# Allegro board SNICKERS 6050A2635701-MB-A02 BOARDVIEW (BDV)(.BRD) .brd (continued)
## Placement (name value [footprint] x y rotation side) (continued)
R3076  10K_5%_2  [RSC_100X050X040_2]  89.19 86.85 90 bottom
R3077  0_5%_2_DY  [RSC_100X050X040_2]  93.89 89.14 180 bottom
R3078  10K_5%_2_DY  [RSC_100X050X040_2]  77.56 86.74 180 top
R3081  0_5%_2  [RSC_100X050X040_2]  91 87.2 90 bottom
R3082  0_5%_2  [RSC_100X050X040_2]  76.49 89.14 270 top
R3083  0_5%_2  [RSC_100X050X040_2]  74.71 89.14 270 top
R3092  0_5%_2  [RSC_100X050X040_2]  91.46 91.67 180 top
R3093  10K_5%_2_DY  [RSC_100X050X040_2]  76.23 86.85 90 top
R3094  10K_5%_2_DY  [RSC_100X050X040_2]  77.38 89.14 90 top
R3095  10K_5%_2_DY  [RSC_100X050X040_2]  75.6 89.14 90 top
R3301  100K_5%_2  [RSC_100X050X040_2]  317.91 25.89 0 bottom
R3302  5.1M_5%_2  [RSC_100X050X040_2]  317.91 25 180 bottom
R3303  100K_5%_2  [RSC_100X050X040_2]  317.91 27.67 180 bottom
R3304  1M_5%_2  [RSC_100X050X040_2]  317.91 28.56 180 bottom
R3305  100_5%_2  [RSC_100X050X040_2]  315.5 41.01 90 top
R3501  0_5%_2_DY  [RSC_100X050X040_2]  124.49 147.43 270 top
R3502  4.7K_5%_2  [RSC_100X050X040_2]  126.65 147.43 90 top
R3503  4.7K_5%_2  [RSC_100X050X040_2]  129.19 146.92 90 bottom
R3507  0_5%_2_DY  [RSC_100X050X040_2]  122.71 147.43 270 top
R3510  0_5%_2_DY  [RSC_100X050X040_2]  130.21 147.43 90 top
R3511  short_0402_15  [RSC_100X050X040_2_15_SHORT]  128.43 147.43 90 top
R3516  0_5%_2_DY  [RSC_100X050X040_2]  129.32 147.43 90 top
R3600  0_5%_2  [RSC_100X050X040_2]  311.31 118.22 0 top
R4100  10K_5%_2  [RSC_100X050X040_2]  200.44 135.11 180 top
R4101  10K_5%_2  [RSC_100X050X040_2]  203.74 134.22 0 top
R4103  10K_5%_2_DY  [RSC_100X050X040_2]  202.09 134.22 0 top
R4104  0_5%_2_DY  [RSC_100X050X040_2]  206.79 145.02 0 top
R4105  2_1%_2  [RSC_100X050X040_2]  252.64 142.23 270 top
R4106  1.8K_1%_2  [RSC_100X050X040_2]  211.74 144.77 90 top
R4107  0_5%_2_DY  [RSC_100X050X040_2]  253.52 142.23 90 top
R4108  1.8K_1%_2  [RSC_100X050X040_2]  255.3 142.23 270 top
R4109  1.8K_1%_2  [RSC_100X050X040_2]  259.11 142.23 90 top
R4110  24.9_1%_2  [RSC_100X050X035_2]  249.59 141.72 90 top
R4111  24.9_1%_2  [RSC_100X050X035_2]  189.9 146.92 0 top
R4112  2_1%_2  [RSC_100X050X040_2]  188.25 146.04 0 top
R4114  10K_5%_2  [RSC_100X050X040_2]  178.21 147.31 270 top
R4115  10K_5%_2_DY  [RSC_100X050X040_2]  178.21 145.65 270 top
R4116  10K_5%_2  [RSC_100X050X040_2]  131.73 147.43 270 top
R4117  64.9_1%_2  [RSC_100X050X040_2]  223.93 143.37 0 top
R4118  64.9_1%_2  [RSC_100X050X040_2]  223.93 142.48 0 top
R4119  64.9_1%_2  [RSC_100X050X040_2]  149.38 147.31 270 bottom
R4120  64.9_1%_2  [RSC_100X050X040_2]  147.73 147.31 270 bottom
R4121  330_5%_2  [RSC_100X050X040_2]  132.87 147.43 270 top
R4122  1.8K_1%_2  [RSC_100X050X040_2]  210.85 144.77 270 top
R4123  100K_5%_2  [RSC_100X050X040_2]  129.45 144.89 90 top
R4125  10K_5%_2  [RSC_100X050X040_2]  125.46 134.94 0 top
R4126  10K_5%_2  [RSC_100X050X040_2]  123.83 134.94 180 top
R4131  1.8K_1%_2  [RSC_100X050X040_2]  188.25 146.92 180 top
R4132  1.8K_1%_2  [RSC_100X050X040_2]  185.83 146.04 180 top
R4134  0_5%_2_DY  [RSC_100X050X040_2]  188.25 145.15 180 top
R4136  24.9_1%_2  [RSC_100X050X035_2]  227.36 101.08 0 top
R4200  10K_5%_2  [RSC_100X050X040_2]  123.86 139.69 0 top
R4301  10K_5%_2  [RSC_100X050X040_2]  115.09 161.28 0 bottom
R4302  22_5%_2  [RSC_100X050X040_2]  115.09 159.5 180 bottom
R4303  10K_5%_2  [RSC_100X050X040_2]  117.13 157.34 0 bottom
R4411  39K_1%_2  [RSC_100X050X040_2]  48.93 88.63 270 top
R4412  150_1%_2  [RSC_100X050X040_2]  49.82 85.84 90 top
R4503  2_1%_2  [RSC_100X050X040_2]  227.36 103.11 180 top
R4507  51_5%_2_DY  [RSC_100X050X040_2]  223.36 75.47 0 top
R4508  51_5%_2_DY  [RSC_100X050X040_2]  223.35 77.82 0 top
R4509  51_5%_2  [RSC_100X050X040_2]  223.36 72.74 180 top
R4515  56_5%_2  [RSC_100X050X040_2]  223.3 79.87 180 top
R4516  100K_5%_2_DY  [RSC_100X050X040_2]  223.81 84.69 180 top
R4517  62_5%_2  [RSC_100X050X040_2]  225.08 79.61 180 top
R4518  200_1%_2  [RSC_100X050X040_2]  218.43 93.15 90 bottom
R4519  49.9_1%_2  [RSC_100X050X040_2]  211.49 83.68 0 top
R4520  49.9_1%_2  [RSC_100X050X040_2]  186.34 95.87 0 top
R4521  100_1%_2  [RSC_100X050X040_2]  211.49 74.15 90 top
R4522  100_1%_2  [RSC_100X050X040_2]  212.5 74.15 90 top
R4523  1K_5%_2  [RSC_100X050X040_2]  209.96 86.85 180 top
R4524  75_1%_2  [RSC_100X050X040_2]  212.12 78.09 0 top
R4525  43_5%_2  [RSC_100X050X040_2]  212.24 79.43 270 top
R4526  51_5%_2_DY  [RSC_100X050X040_2]  225.08 93.97 0 top
R4527  10K_5%_2_DY  [RSC_100X050X040_2]  216.82 72.25 180 bottom
R4534  1K_1%_2_DY  [RSC_100X050X040_2]  211.74 85.2 180 top
R4535  short_0402_15  [RSC_100X050X040_2_15_SHORT]  158.4 85.96 0 top
R4540  100_1%_2  [RSC_100X050X040_2]  217.53 93.15 90 bottom
R4541  120_1%_2  [RSC_100X050X040_2]  219.34 93.15 90 bottom
R4544  24.9_1%_2  [RSC_100X050X035_2]  186.72 70.34 270 bottom
R4550  short_0402_5  [RSC_100X050X040_2_SHORT]  141.51 100.7 270 top
R4553  470_5%_2  [RSC_100X050X040_2]  148.75 92.82 180 bottom
R4568  0_5%_2_DY  [RSC_100X050X040_2]  223.36 71.81 0 top
R4569  short_0402_15  [RSC_100X050X040_2_15_SHORT]  223.36 74.55 0 top
R4571  10K_5%_2  [RSC_100X050X040_2]  164.24 74.28 0 top
R4572  10K_5%_2_DY  [RSC_100X050X040_2]  164.75 77.91 180 top
R4573  8.2K_5%_2  [RSC_100X050X040_2]  158.4 78.79 0 top
R4574  8.2K_5%_2_DY  [RSC_100X050X040_2]  158.4 77.9 0 top
R4575  8.2K_5%_2_DY  [RSC_100X050X040_2]  163.1 79.23 0 bottom
R4576  8.2K_5%_2  [RSC_100X050X040_2]  162.59 78.34 0 bottom
R4577  8.2K_5%_2_DY  [RSC_100X050X040_2]  158.47 79.49 0 bottom
R4578  8.2K_5%_2  [RSC_100X050X040_2]  158.47 78.58 0 bottom
R4588  short_0402_5  [RSC_100X050X040_2_SHORT]  142.91 100.19 180 bottom
R4590  150_5%_2  [RSC_100X050X040_2]  223.35 76.53 0 top
R4593  10K_5%_2  [RSC_100X050X040_2]  216.82 71.36 0 bottom
R4700  10K_5%_2  [RSC_100X050X040_2]  168.82 94.85 0 bottom
R4701  short_0402_15  [RSC_100X050X040_2_15_SHORT]  153.83 80.12 180 top
R4705  10K_5%_2  [RSC_100X050X040_2]  153.83 76.31 0 bottom
R4706  10K_5%_2_DY  [RSC_100X050X040_2]  163.02 83.02 0 bottom
R4707  10K_5%_2  [RSC_100X050X040_2]  163.1 80.25 0 bottom
R4708  10K_5%_2  [RSC_100X050X040_2]  158.47 85.1 180 bottom
R4709  10K_5%_2  [RSC_100X050X040_2]  163.02 85.81 0 bottom
R4711  10K_5%_2  [RSC_100X050X040_2]  158.4 79.68 0 top
R4712  10K_5%_2  [RSC_100X050X040_2]  153.83 83.17 0 top
R4713  100K_5%_2  [RSC_100X050X040_2]  142.15 88.38 0 bottom
R4714  10K_5%_2  [RSC_100X050X040_2]  168.82 96.63 0 bottom
R4715  10K_5%_2  [RSC_100X050X040_2]  158.47 81.34 0 bottom
R4717  10K_5%_2  [RSC_100X050X040_2]  153.83 91.93 180 top
R4718  short_0402_5  [RSC_100X050X040_2_SHORT]  158.4 92.95 180 top
R4720  10K_5%_2_DY  [RSC_100X050X040_2]  166.15 94.73 0 bottom
R4721  10K_5%_2_DY  [RSC_100X050X040_2]  158.45 96.1 0 bottom
R4722  0_5%_2_DY  [RSC_100X050X040_2]  158.39 83.29 0 top
R4723  short_0402_5  [RSC_100X050X040_2_SHORT]  158.39 82.4 0 top
R4724  10K_5%_2  [RSC_100X050X040_2]  163.01 94.29 0 bottom
R4725  10K_5%_2  [RSC_100X050X040_2]  158.39 84.18 0 top
R4726  10K_5%_2_DY  [RSC_100X050X040_2]  170.85 81.9 180 top
R4727  8.2K_5%_2  [RSC_100X050X040_2]  158.47 84.17 180 bottom
R4728  10K_5%_2  [RSC_100X050X040_2]  153.83 78.34 0 top
R4729  200K_5%_2  [RSC_100X050X040_2]  158.47 86.93 0 bottom
R4730  10K_5%_2_DY  [RSC_100X050X040_2]  158.47 76.72 180 bottom
R4731  10K_5%_2  [RSC_100X050X040_2]  158.47 77.64 180 bottom
R4732  1K_5%_2  [RSC_100X050X040_2]  223.36 73.66 0 top
R4733  1K_5%_2  [RSC_100X050X040_2]  158.46 89.72 0 bottom
R4734  10K_5%_2  [RSC_100X050X040_2]  163.01 92.45 0 bottom
R4735  10K_5%_2  [RSC_100X050X040_2]  166.78 73.52 180 bottom
R4736  10K_5%_2  [RSC_100X050X040_2]  158.32 95.21 0 bottom
R4737  10K_5%_2_DY  [RSC_100X050X040_2]  158.45 92.42 180 bottom
R4738  10K_5%_2  [RSC_100X050X040_2]  153.83 75.68 180 top
R4741  10K_5%_2  [RSC_100X050X040_2]  158.45 91.53 0 bottom
R4742  330K_5%_2  [RSC_100X050X040_2]  173.26 100.44 0 bottom
R4743  100K_5%_2  [RSC_100X050X040_2]  158.4 95.87 0 top
R4744  10K_5%_2  [RSC_100X050X040_2]  158.45 96.99 0 bottom
R4745  10K_5%_2  [RSC_100X050X040_2]  153.83 74.79 180 top
R4746  100K_5%_2_DY  [RSC_100X050X040_2]  166.15 98.54 0 bottom
R4747  10K_5%_2  [RSC_100X050X040_2]  158.45 93.43 0 bottom
R4748  49.9_1%_2  [RSC_100X050X040_2]  186.34 94.47 0 top
R4749  10K_5%_2  [RSC_100X050X040_2]  158.66 74.41 0 top
R4750  10K_5%_2  [RSC_100X050X040_2]  169.83 71.61 180 bottom
R4751  10K_5%_2_DY  [RSC_100X050X040_2]  158.47 80.41 0 bottom
R4752  10K_5%_2  [RSC_100X050X040_2]  166.78 71.23 180 bottom
R4753  10K_5%_2  [RSC_100X050X040_2]  163.02 84.88 0 bottom
R4754  10K_5%_2  [RSC_100X050X040_2]  153.83 77.46 180 top
R4755  10K_5%_2  [RSC_100X050X040_2]  158.4 72.76 180 bottom
R4756  22.6_1%_2  [RSC_100X050X040_2]  158.4 94.98 180 top
R4757  10K_5%_2  [RSC_100X050X040_2]  153.83 72.76 180 bottom
R4758  100K_5%_2  [RSC_100X050X040_2]  167.55 69.45 180 bottom
R4759  100K_5%_2  [RSC_100X050X040_2]  168.56 66.79 180 bottom
R4760  10K_5%_2_DY  [RSC_100X050X040_2]  153.83 73.65 180 bottom
R4761  10K_5%_2_DY  [RSC_100X050X040_2]  153.83 74.53 180 bottom
R4762  10K_5%_2_DY  [RSC_100X050X040_2]  153.83 71.87 180 bottom
R4763  10K_5%_2  [RSC_100X050X040_2]  153.83 70.98 180 bottom
R4764  10K_5%_2  [RSC_100X050X040_2]  153.83 79.23 180 top
R4765  10K_5%_2  [RSC_100X050X040_2]  158.47 83.25 180 bottom
R4767  10K_5%_2_DY  [RSC_100X050X040_2]  170.85 82.79 180 top
R4769  10K_5%_2_DY  [RSC_100X050X040_2]  169.83 70.72 0 bottom
R4770  10K_5%_2  [RSC_100X050X040_2]  164.24 76.06 0 top
R4771  10K_5%_2  [RSC_100X050X040_2]  172.24 60.95 180 top
R4774  22_5%_2  [RSC_100X050X040_2]  164.24 106.69 270 top
R4775  10K_5%_2  [RSC_100X050X040_2]  193.71 69.71 180 bottom
R4776  2.2K_5%_2  [RSC_100X050X040_2]  153.83 88.63 0 bottom
R4778  10K_5%_2  [RSC_100X050X040_2]  166.15 97.65 180 bottom
R4780  10K_5%_2  [RSC_100X050X040_2]  169.83 69.71 0 bottom
R4781  8.2K_5%_2  [RSC_100X050X040_2]  164.24 75.17 0 top
R4782  10K_5%_2  [RSC_100X050X040_2]  261.02 76.57 0 bottom
R4783  2.2K_5%_2  [RSC_100X050X040_2]  148.88 86.98 180 bottom
R4785  10K_5%_2  [RSC_100X050X040_2]  153.83 76.57 180 top
R4786  2.2K_5%_2  [RSC_100X050X040_2]  175.17 69.38 180 bottom
R4787  2.2K_5%_2  [RSC_100X050X040_2]  171.74 66.79 180 bottom
R4788  2.2K_5%_2  [RSC_100X050X040_2]  168.56 67.68 180 bottom
R4789  2.2K_5%_2  [RSC_100X050X040_2]  175.17 68.49 180 bottom
R4790  short_0402_5  [RSC_100X050X040_2_SHORT]  146.59 82.49 0 bottom
R4791  10K_5%_2  [RSC_100X050X040_2]  193.71 70.6 180 bottom
R4792  2.2K_5%_2  [RSC_100X050X040_2]  153.83 83.93 180 bottom
R4793  33_5%_2  [RSC_100X050X040_2]  164.98 81.97 0 bottom
R4794  33_5%_2  [RSC_100X050X040_2]  158.46 87.87 0 bottom
R4795  33_5%_2  [RSC_100X050X040_2]  166.57 88.83 0 bottom
R4796  33_5%_2  [RSC_100X050X040_2]  163.02 87.64 0 bottom
R4797  2.2K_5%_2  [RSC_100X050X040_2]  148.88 88.38 0 bottom
R4798  10K_5%_2  [RSC_100X050X040_2]  163.01 89.46 0 bottom
R4799  short_0402_5  [RSC_100X050X040_2_SHORT]  167.67 86.47 90 top
R4800  10K_5%_2  [RSC_100X050X040_2]  153.83 95.36 0 top
R4801  10K_5%_2  [RSC_100X050X040_2]  155.45 95.36 180 top
R4802  short_0402_5  [RSC_100X050X040_2_SHORT]  163.01 90.35 0 bottom
R4803  10K_5%_2  [RSC_100X050X040_2]  158.66 72.63 0 top
R4804  10K_5%_2  [RSC_100X050X040_2]  158.66 73.52 0 top
R4805  10K_5%_2  [RSC_100X050X040_2]  158.66 71.74 0 top
R4806  10K_5%_2_DY  [RSC_100X050X040_2]  153.83 79.87 180 bottom
R4807  51_5%_2  [RSC_100X050X040_2]  211.74 86.6 180 top
R4808  51_5%_2_DY  [RSC_100X050X040_2]  240.32 88.63 0 top
R4809  10K_5%_2_DY  [RSC_100X050X040_2]  153.83 78.09 180 bottom
R4810  10K_5%_2  [RSC_100X050X040_2]  153.83 80.76 180 bottom
R4811  0_5%_2  [RSC_100X050X040_2]  186.6 66.66 270 bottom
R4812  3K_1%_2  [RSC_100X050X040_2]  186.72 68.31 90 bottom
R4813  10K_5%_2  [RSC_100X050X040_2]  153.83 77.2 180 bottom
R4814  10K_5%_2_DY  [RSC_100X050X040_2]  153.83 78.98 180 bottom
R4815  short_0402_5  [RSC_100X050X040_2_SHORT]  166.15 99.43 180 bottom
R4816  10K_5%_2  [RSC_100X050X040_2]  163.02 82.09 0 bottom
R4817  10K_5%_2  [RSC_100X050X040_2]  163.02 81.16 180 bottom
R4818  10K_5%_2  [RSC_100X050X040_2]  163.02 83.96 0 bottom
R4820  43K_1%_2  [RSC_100X050X040_2]  163.01 88.58 180 bottom
R4821  110_1%_2  [RSC_100X050X040_2]  212.12 80.88 0 top
R4822  short_0402_5  [RSC_100X050X040_2_SHORT]  240.19 91.17 180 top
R4823  1K_5%_2  [RSC_100X050X040_2]  240.19 90.28 0 top
R4824  10K_5%_2_DY  [RSC_100X050X040_2]  164.75 88.63 0 bottom
R4825  10K_5%_2  [RSC_100X050X040_2]  162.97 98.28 180 bottom
R4827  2.2K_5%_2  [RSC_100X050X040_2]  144.05 85.84 0 bottom
R4828  2.2K_5%_2  [RSC_100X050X040_2]  148.89 84.55 180 bottom
R4829  2.2K_5%_2_DY  [RSC_100X050X040_2]  153.83 92.95 180 top
R4830  2.2K_5%_2  [RSC_100X050X040_2]  148.88 85.46 0 bottom
R4831  1M_5%_2  [RSC_100X050X040_2]  144.94 99.68 0 bottom
R4832  1K_5%_2  [RSC_100X050X040_2]  141.38 101.2 0 bottom
R4833  1M_5%_2  [RSC_100X050X040_2]  144.94 100.57 0 bottom
R4834  20K_5%_2  [RSC_100X050X040_2]  145.45 102.09 180 bottom
R4835  0_5%_2_DY  [RSC_100X050X040_2]  153.83 86.09 0 bottom
R4836  0_5%_2_DY  [RSC_100X050X040_2]  148.88 83.55 0 bottom
R4838  2.2K_5%_2_DY  [RSC_100X050X040_2]  254.03 100.06 180 top
R4839  10K_5%_2  [RSC_100X050X040_2]  263.68 59.8 90 top
R4840  10K_5%_2  [RSC_100X050X040_2]  166.15 96.76 180 bottom
R4841  8.2K_5%_2  [RSC_100X050X040_2]  180.25 75.04 270 top
R4842  330K_5%_2  [RSC_100X050X040_2]  173.26 101.33 0 bottom
R4845  33K_5%_2  [RSC_100X050X040_2]  144.94 98.79 0 bottom
R4850  0_5%_2_DY  [RSC_100X050X040_2]  181.01 80 180 top
R4852  3.01K_1%_2  [RSC_100X050X040_2]  179.1 70.34 270 bottom
R4855  0_5%_2_DY  [RSC_100X050X040_2]  172.24 83.81 180 top
R4856  2.2K_5%_2  [RSC_100X050X040_2]  144.05 84.69 180 bottom
R4857  10K_5%_2  [RSC_100X050X040_2]  168.82 95.74 0 bottom
R4858  0_5%_3  [RSC_160X080X055_2]  189.39 81.65 90 top
R4859  10K_5%_2  [RSC_100X050X040_2]  166.78 72.12 180 bottom
R4860  short_0402_5  [RSC_100X050X040_2_SHORT]  162.97 96.51 0 bottom
R4861  1K_5%_2  [RSC_100X050X040_2]  151.54 106.54 0 top
R4862  10M_5%_2  [RSC_100X050X040_2]  165.77 102.09 270 bottom
R4863  10K_5%_2  [RSC_100X050X040_2]  151.54 107.94 0 top
R4866  short_0402_5  [RSC_100X050X040_2_SHORT]  153.83 81.65 0 bottom
R4867  1K_5%_2  [RSC_100X050X040_2]  151.8 80 90 bottom
R4868  short_0402_5  [RSC_100X050X040_2_SHORT]  277.27 93.46 270 top
R4869  33_5%_2  [RSC_100X050X040_2]  163.61 109.21 90 top
R4874  0_5%_2_DY  [RSC_100X050X040_2]  162.72 109.21 90 top
R4875  0_5%_2_DY  [RSC_100X050X040_2]  181.9 84.82 90 top
R4876  330K_5%_2_DY  [RSC_100X050X040_2]  173.01 102.22 0 bottom
R4877  0_5%_2_DY  [RSC_100X050X040_2]  178.87 85.96 270 top
R4880  10K_5%_2_DY  [RSC_100X050X040_2]  158.47 86.02 0 bottom
R4884  2.2K_5%_2  [RSC_100X050X040_2]  153.83 86.98 180 bottom
R4886  51_5%_2  [RSC_100X050X040_2]  211.87 89.39 0 top
R4891  51_5%_2  [RSC_100X050X040_2]  211.87 88.5 0 top
R4892  3K_1%_2  [RSC_100X050X040_2]  190.28 70.22 270 bottom
R4898  1M_5%_2  [RSC_100X050X040_2]  188.82 68.33 0 bottom
R4899  10K_5%_2  [RSC_100X050X040_2]  153.45 109.84 180 top
R4900  1K_5%_2  [RSC_100X050X040_2]  164.37 69.2 270 bottom
R4901  33_5%_2  [RSC_100X050X040_2]  175.17 101.13 0 bottom
R4903  33_5%_2  [RSC_100X050X040_2]  175.17 103.8 0 bottom
R4904  680_5%_2  [RSC_100X050X040_2]  165.26 71.87 90 bottom
R4906  10K_5%_2  [RSC_100X050X040_2]  158.4 71.87 180 bottom
R4907  10K_5%_2  [RSC_100X050X040_2]  159.93 74.79 90 top
R4908  10K_5%_2  [RSC_100X050X040_2]  158.46 88.8 0 bottom
R4909  10K_5%_2  [RSC_100X050X040_2]  158.45 94.32 0 bottom
R4910  33_5%_2  [RSC_100X050X040_2]  175.17 102.02 0 bottom
R4911  10K_5%_2  [RSC_100X050X040_2]  163.01 91.37 0 bottom
R4912  10K_5%_2  [RSC_100X050X040_2]  158.47 82.33 180 bottom
R4913  2.2K_5%_2  [RSC_100X050X040_2]  153.83 85.2 180 bottom
R4914  10K_5%_2  [RSC_100X050X040_2]  158.4 87.87 0 top
R4915  10K_5%_2  [RSC_100X050X040_2]  158.39 88.77 0 top
R4916  10K_5%_2  [RSC_100X050X040_2]  158.39 81.51 0 top
R4917  10K_5%_2  [RSC_100X050X040_2]  158.4 94.09 0 top
R4918  10K_5%_2  [RSC_100X050X040_2]  153.83 94.35 180 top
R4919  10K_5%_2_DY  [RSC_100X050X040_2]  163.02 86.73 180 bottom
R4920  51_5%_2  [RSC_100X050X040_2]  223.35 78.74 0 top
R4921  1K_5%_2_DY  [RSC_100X050X040_2]  228.22 88.13 180 top
R4922  1K_5%_2  [RSC_100X050X040_2]  228.22 89.02 0 top
R4923  10K_5%_2  [RSC_100X050X040_2]  240.32 86.47 0 top
R4924  10K_5%_2  [RSC_100X050X040_2]  153.83 75.42 0 bottom
R4925  short_0402_5  [RSC_100X050X040_2_SHORT]  153.82 88.97 180 top
R4926  1K_5%_2_DY  [RSC_100X050X040_2]  240.32 85.58 180 top
R4929  10K_5%_2_DY  [RSC_100X050X040_2]  158.4 75.68 0 bottom
R4931  1K_5%_2  [RSC_100X050X040_2]  242.86 87.23 270 top
R4934  short_0402_5  [RSC_100X050X040_2_SHORT]  153.83 90.92 0 top
R4936  short_0402_5  [RSC_100X050X040_2_SHORT]  157.89 106.79 90 top
R4937  0_5%_2_DY  [RSC_100X050X040_2]  226.06 86.23 180 top
R4938  0_5%_2_DY  [RSC_100X050X040_2]  226.06 87.11 180 top
R4939  1K_5%_2_DY  [RSC_100X050X040_2]  227.87 90.28 180 top
R4960  10K_5%_2  [RSC_100X050X040_2]  163.01 93.37 0 bottom
R4961  10K_5%_2  [RSC_100X050X040_2]  166.15 95.62 0 bottom
R4996  22_5%_2  [RSC_100X050X040_2]  129.57 86.85 90 top
R4997  22_5%_2  [RSC_100X050X040_2]  120.94 147.43 270 top
R5032  2.2K_5%_2  [RSC_100X050X040_2]  118.44 92.45 180 bottom
R5039  2.2K_5%_2  [RSC_100X050X040_2]  112.16 95.22 90 bottom
R5043  10K_5%_2  [RSC_100X050X040_2]  118.44 93.34 180 bottom
R5044  2.2K_5%_2  [RSC_100X050X040_2]  118.44 91.56 180 bottom
R5049  short_0402_5  [RSC_100X050X040_2_SHORT]  113.05 95.22 270 bottom
R5301  4.7K_5%_2_DY  [RSC_100X050X040_2]  282.23 64.12 270 bottom
R5302  4.7K_5%_2_DY  [RSC_100X050X040_2]  281.97 66.53 270 bottom
R5303  4.7K_5%_2_DY  [RSC_100X050X040_2]  283.62 63.49 270 bottom
R5304  4.7K_5%_2_DY  [RSC_100X050X040_2]  282.86 66.53 270 bottom
R5305  4.7K_5%_2_DY  [RSC_100X050X040_2]  284.51 63.49 270 bottom
R5306  4.7K_5%_2_DY  [RSC_100X050X040_2]  284 66.53 270 bottom
R5307  4.7K_5%_2_DY  [RSC_100X050X040_2]  286.16 63.49 270 bottom
R5308  4.7K_5%_2_DY  [RSC_100X050X040_2]  284.89 66.53 270 bottom
R5309  4.7K_5%_2_DY  [RSC_100X050X040_2]  279.05 66.53 90 bottom
R5310  4.7K_5%_2_DY  [RSC_100X050X040_2]  279.94 66.53 90 bottom
R5311  4.7K_5%_2_DY  [RSC_100X050X040_2]  278.16 66.53 90 bottom
R5312  4.7K_5%_2_DY  [RSC_100X050X040_2]  277.27 68.06 270 bottom
R5313  4.7K_5%_2_DY  [RSC_100X050X040_2]  277.02 70.22 90 top
R5314  4.7K_5%_2_DY  [RSC_100X050X040_2]  277.02 71.87 270 top
R5315  4.99K_1%_2  [RSC_100X050X040_2]  279.05 80.38 90 bottom
R5316  100K_5%_2_DY  [RSC_100X050X040_2]  287.61 79.92 0 bottom
R5317  100K_5%_2  [RSC_100X050X040_2]  287.63 79 0 bottom
R5318  4.7K_5%_2  [RSC_100X050X040_2]  277.53 78.34 0 bottom
R5319  100K_5%_2_DY  [RSC_100X050X040_2]  287.56 77.96 180 bottom
R5320  100K_5%_2  [RSC_100X050X040_2]  287.6 80.84 0 bottom
R5403  4.7K_5%_2  [RSC_100X050X040_2]  266.86 64.5 270 bottom
R5407  4.7K_5%_2  [RSC_100X050X040_2]  268.76 66.66 270 bottom
R5409  4.7K_5%_2_DY  [RSC_100X050X040_2]  264.07 66.66 90 bottom
R5410  4.7K_5%_2_DY  [RSC_100X050X040_2]  264.95 66.66 90 bottom
R5415  4.99K_1%_2  [RSC_100X050X040_2]  263.81 80.5 90 bottom
R5416  100K_5%_2  [RSC_100X050X040_2]  268.26 80.5 270 bottom
R5417  100K_5%_2  [RSC_100X050X040_2]  267.37 80.5 90 bottom
R5418  4.7K_5%_2  [RSC_100X050X040_2]  261.02 75.3 0 bottom
R5419  4.7K_5%_2_DY  [RSC_100X050X040_2]  271.44 74.24 0 bottom
R5420  1M_5%_2  [RSC_100X050X040_2]  271.44 73.36 0 bottom
R5421  4.7K_5%_2_DY  [RSC_100X050X040_2]  271.46 75.59 0 bottom
R5422  1M_5%_2  [RSC_100X050X040_2]  271.46 76.48 0 bottom
R5423  100K_5%_2_DY  [RSC_100X050X040_2]  269.78 80.5 90 bottom
R5424  100K_5%_2  [RSC_100X050X040_2]  269.78 78.85 270 bottom
R5425  100K_5%_2  [RSC_100X050X040_2]  270.67 80.5 270 bottom
R5426  100K_5%_2_DY  [RSC_100X050X040_2]  270.67 78.85 90 bottom
R6000  0.01_1%_6  [RSC_320X160X080_4]  287.56 139.3 180 top
R6001  0.02_1%_6  [RSC_320X160X160_4]  274.23 133.46 90 bottom
R6005  100K_5%_2  [RSC_100X050X040_2]  303.82 145.15 180 top
R6015  0_5%_2  [RSC_100X050X040_2]  287.43 122.92 270 top
R6016  220K_5%_2  [RSC_100X050X040_2]  306.23 146.42 90 top
R6017  220K_5%_2  [RSC_100X050X040_2]  301.91 142.99 90 top
R6018  4.3K_5%_2  [RSC_100X050X040_2]  291.75 143.24 180 top
R6020  short_0402_15  [RSC_100X050X040_2_15_SHORT]  283.5 128 180 top
R6021  127K_1%  [RSC_100X050X040_2]  289.72 133.34 270 top
R6022  1M_5%_2  [RSC_100X050X040_2]  288.7 131.68 270 top
R6023  20K_1%_2  [RSC_100X050X040_2]  288.7 133.34 90 top
R6024  22K_5%_2  [RSC_100X050X040_2]  289.72 131.68 270 top
R6025  short_0402_15  [RSC_100X050X040_2_15_SHORT]  283.5 127.11 180 top
R6027  10_5%_5  [RSC_200X125X115_2]  291.19 122.29 90 top
R6028  4.3K_5%_2  [RSC_100X050X040_2]  301.53 144.77 270 top
R6029  18.2K_1%_2  [RSC_100X050X040_2]  292.26 133.21 270 top
R6030  10K_1%_2  [RSC_100X050X040_2]  292.26 130.67 270 top
R6049  10K_5%_2  [RSC_100X050X040_2]  283.5 129.78 0 top
R6051  100_5%_2  [RSC_100X050X040_2]  165.89 60.95 180 top
R6053  100_5%_2  [RSC_100X050X040_2]  164.24 60.95 180 top
R6057  1K_5%_2  [RSC_100X050X040_2]  161.83 60.95 0 top
R6058  100K_5%_2  [RSC_100X050X040_2]  159.93 60.95 0 top
R6074  100K_5%_2  [RSC_100X050X040_2]  280.19 113.9 90 top
R6110  10K_5%_2_DY  [RSC_100X050X040_2]  204.88 158.1 0 bottom
R6115  2.2_5%_3  [RSC_160X080X080_2]  202.85 158.48 90 bottom
R6149  short_0402_15  [RSC_100X050X040_2_15_SHORT]  206.79 158.1 180 bottom
R6150  RSC_0402_DY  [RSC_100X050X040_2]  233.19 152.31 90 bottom
R6151  10K_1%_2_DY  [RSC_100X050X040_2]  241.84 147.05 0 top
R6160  10K_5%_2_DY  [RSC_100X050X040_2]  240.19 147.05 0 top
R6161  short_0402_15  [RSC_100X050X040_2_15_SHORT]  228.63 148.4 180 bottom
R6165  2.2_5%_3  [RSC_160X080X080_2]  241.33 150.23 0 bottom
R6166  RSC_0402_DY  [RSC_100X050X040_2]  235.15 150.46 180 bottom
R6167  0_5%_2_DY  [RSC_100X050X040_2]  234.56 151.73 0 bottom
R6199  short_0402_15  [RSC_100X050X040_2_15_SHORT]  241.84 147.94 180 top
R6200  14K_1%_2  [RSC_100X050X040_2]  150.27 158.61 0 bottom
R6201  20K_1%_2  [RSC_100X050X040_2]  150.27 157.72 180 bottom
R6207  short_0402_15  [RSC_100X050X040_2_15_SHORT]  151.04 161.15 180 top
R6209  short_0402_5  [RSC_100X050X040_2_SHORT]  150.27 156.83 0 bottom
R6210  10_5%_2  [RSC_100X050X040_2]  154.08 154.16 270 bottom
R6211  127K_1%  [RSC_100X050X040_2]  151.04 162.04 180 top
R6215  2.2_5%_3  [RSC_160X080X080_2]  155.89 156.53 0 bottom
R6300  6.49K_1%_2  [RSC_100X050X040_2]  119.54 97.78 90 bottom
R6301  20K_1%_2  [RSC_100X050X040_2]  120.43 97.78 270 bottom
R6307  short_0402_15  [RSC_100X050X040_2_15_SHORT]  121.44 100.57 90 bottom
R6309  short_0402_5  [RSC_100X050X040_2_SHORT]  119.79 97.14 270 top
R6310  10_5%_2  [RSC_100X050X040_2]  123.48 94.73 270 top
R6311  88.7K_1%_2  [RSC_100X050X040_2]  120.56 100.57 90 bottom
R6315  2.2_5%_3  [RSC_160X080X080_2]  126.02 94.6 0 bottom
R6350  15K_1%_2  [RSC_100X050X040_2]  103.92 142.61 0 top
R6351  10K_1%_2  [RSC_100X050X040_2]  103.54 144.38 0 top
R6450  11K_1%_2  [RSC_100X050X040_2]  247.43 83.17 270 top
R6451  10K_1%_2  [RSC_100X050X040_2]  248.32 83.17 270 top
R6612  RSC_0402_DY  [RSC_100X050X040_2]  236.63 78.85 270 bottom
R6615  2.2_5%_3  [RSC_160X080X080_2]  240.65 66.74 0 bottom
R6616  2.32K_1%  [RSC_100X050X040_2]  228.95 72.32 90 bottom
R6617  10K_1%_NTC  [RSC_100X050X055_2]  227.67 71.9 180 bottom
R6618  3.01K_1%_2  [RSC_100X050X040_2]  227.67 72.79 0 bottom
R6619  18.7K_1%_2  [RSC_100X050X040_2]  226.4 72.28 270 bottom
R6633  10K_1%_2  [RSC_100X050X040_2]  226.73 88.89 0 bottom
R6640  110_1%_2  [RSC_100X050X040_2]  231.43 86.85 270 bottom
R6641  54.9_1%_2  [RSC_100X050X040_2]  229.27 86.85 270 bottom
R6643  0_5%_2  [RSC_100X050X040_2]  233.83 77.84 0 bottom
R6645  10_5%_2  [RSC_100X050X040_2]  233.82 82.41 0 bottom
R6646  9.31K_1%_2  [RSC_100X050X040_2]  234.6 75.8 90 bottom
R6647  150K_1%_2  [RSC_100X050X040_2]  235.49 75.8 270 bottom
R6649  1.02M_1%_2  [RSC_100X050X040_2]  233.71 75.8 90 bottom
R6650  150K_1%_2  [RSC_100X050X040_2]  232.82 75.8 270 bottom
R6651  2.05K_1%_2  [RSC_100X050X040_2]  226.73 86.85 0 bottom
R6652  RSC_0402_DY  [RSC_100X050X040_2]  231.05 75.8 90 bottom
R6653  150K_1%_2  [RSC_100X050X040_2]  231.93 75.8 270 bottom
R6654  100K_1%_2  [RSC_100X050X040_2]  230.66 74.15 270 bottom
R6655  432K_1%_2  [RSC_100X050X040_2]  229.97 75.8 90 bottom
R6656  10K_1%_2  [RSC_100X050X040_2]  227.24 83.93 0 bottom
R6657  10K_5%_2  [RSC_100X050X040_2]  226.47 77.07 0 bottom
R6658  10K_1%_2  [RSC_100X050X040_2]  228.51 75.17 0 bottom
R6659  RSC_0402_DY  [RSC_100X050X040_2]  226.09 75.63 90 bottom
R6660  39K_1%_2  [RSC_100X050X040_2]  226.98 75.63 90 bottom
R6661  100K_1%_NTC  [RSC_100X050X055_2]  234.22 70.6 270 bottom
R6663  0_5%_2  [RSC_100X050X040_2]  226.47 81.39 180 bottom
R6665  10_5%_2  [RSC_100X050X040_2]  228.12 89.01 90 bottom
R6666  0_5%_2  [RSC_100X050X040_2]  226.47 80.45 0 bottom
R6902  220K_5%_2  [RSC_100X050X040_2]  300.01 135.24 270 top
R6903  130K_1%_2  [RSC_100X050X040_2]  299.12 134.48 90 top
R6904  45.3K_1%_2  [RSC_100X050X040_2]  289.59 99.81 0 top
R6909  8.66K_1%_2  [RSC_100X050X040_2]  289.59 100.7 180 top
R6910  6.04K_1%_1/16W_2  [RSC_100X050X040_2]  289.59 98.03 0 top
R6913  46.4K_1%_2  [RSC_100X050X040_2]  284 131.68 270 top
R6914  47K_5%_2  [RSC_100X050X040_2]  61.88 85.2 270 top
R6915  100K_5%_2  [RSC_100X050X040_2]  64.04 89.39 90 top
R6916  RSC_0402_DY  [RSC_100X050X040_2]  64.93 89.65 90 top
R6917  619_1%_2  [RSC_100X050X040_2]  56.27 85.71 270 top
R6918  2.1K_1%_2  [RSC_100X050X040_2]  55.79 89.14 270 top
R6930  86.6K_1%_2  [RSC_100X050X040_2]  294.67 135.49 90 top
R6931  200K_1%_2  [RSC_100X050X040_2]  293.4 137.53 270 top
R6933  274K_1%_2  [RSC_100X050X040_2]  298.99 137.53 270 top
R6934  22K_5%_2  [RSC_100X050X040_2]  293.78 135.49 270 top
R6935  47K_5%_2  [RSC_100X050X040_2]  299.88 137.53 90 top
R6936  3.24K_1%_2  [RSC_100X050X040_2]  56.27 83.81 90 top
R6990  RSC_0402_DY  [RSC_100X050X040_2]  282.23 131.68 270 top
R6994  49.9K_1%_2  [RSC_100X050X040_2]  293.91 128.64 270 top
R6995  576K_1%_2  [RSC_100X050X040_2]  293.91 130.67 270 top
R6996  49.9K_1%_2  [RSC_100X050X040_2]  293.15 133.21 270 top
R6998  13K_1%_2  [RSC_100X050X040_2]  289.59 98.92 180 top
R6999  100K_5%_2  [RSC_100X050X040_2]  287.43 101.08 180 top
R7000  100_5%_2  [RSC_100X050X040_2]  211.11 152.89 270 bottom
R7001  10K_5%_2  [RSC_100X050X040_2]  302.17 131.18 90 top
R7005  200K_5%_2  [RSC_100X050X040_2]  306.99 121.78 0 top
R7010  short_0402_5  [RSC_100X050X040_2_SHORT]  210.98 153.91 180 top
R7012  short_0402_5  [RSC_100X050X040_2_SHORT]  232.32 86.85 90 bottom
R7017  100K_5%_2  [RSC_100X050X040_2]  294.55 126.1 90 top
R7019  short_0402_5  [RSC_100X050X040_2_SHORT]  118.02 96 270 top
R7020  short_0402_5  [RSC_100X050X040_2_SHORT]  99.09 143.24 180 top
R7021  short_0402_5  [RSC_100X050X040_2_SHORT]  209.33 147.18 270 top
R7023  0_5%_2_DY  [RSC_100X050X040_2]  211.11 147.18 270 top
R7050  47_5%_2  [RSC_100X050X040_2]  119.41 90.61 0 bottom
R7100  100_5%_2  [RSC_100X050X040_2]  301.15 107.43 0 top
R7101  470K_5%_2  [RSC_100X050X040_2]  120.68 88.89 270 bottom
R7110  10K_5%_2  [RSC_100X050X040_2]  212.12 149.97 270 bottom
R7111  100K_5%_2  [RSC_100X050X040_2]  209.33 149.97 90 bottom
R7112  short_0402_5  [RSC_100X050X040_2_SHORT]  213.27 149.97 270 bottom
R7113  short_0402_5  [RSC_100X050X040_2_SHORT]  214.28 149.97 270 bottom
R7114  100K_5%_2  [RSC_100X050X040_2]  210.98 155.94 0 top
R7115  200K_5%_2  [RSC_100X050X040_2]  209.33 155.94 180 top
R7116  short_0402_5  [RSC_100X050X040_2_SHORT]  210.98 155.05 0 top
R7117  short_0402_5  [RSC_100X050X040_2_SHORT]  209.33 155.05 180 top
R7118  short_0402_5  [RSC_100X050X040_2_SHORT]  180.25 151.75 180 bottom
R7119  short_0402_5  [RSC_100X050X040_2_SHORT]  180.25 152.64 180 bottom
R7150  220_5%_2  [RSC_100X050X040_2]  124.24 91.81 270 bottom
R7151  470K_5%_2  [RSC_100X050X040_2]  121.57 88.89 270 bottom
R7152  220_5%_2  [RSC_100X050X040_2]  127.41 87.49 270 bottom
R7153  22_5%_2  [RSC_100X050X040_2]  166.53 147.31 90 top
R7154  200K_5%_2  [RSC_100X050X040_2]  121.7 91.55 270 bottom
R7350  100K_5%_2  [RSC_100X050X040_2]  208.31 147.18 270 top
R7353  100_5%_2  [RSC_100X050X040_2]  106.2 88.63 90 bottom
R7354  470K_5%_2  [RSC_100X050X040_2]  205.65 149.46 90 top
R7355  47_5%_2  [RSC_100X050X040_2]  309.53 116.7 270 top
R7401  53.6K_1%_2  [RSC_100X050X040_2]  244.13 100.44 90 top
R7404  20K_5%_2  [RSC_100X050X040_2]  241.46 112.25 270 top
R7405  38.3K_1%_2  [RSC_100X050X040_2]  247.81 106.16 90 top
R7406  1M_5%_2  [RSC_100X050X040_2]  239.17 105.9 90 top
R7407  1M_5%_2  [RSC_100X050X040_2]  242.35 109.97 90 top
R7408  10K_5%_2  [RSC_100X050X040_2]  242.35 100.44 90 top
R7409  10K_5%_2  [RSC_100X050X040_2]  243.24 109.97 270 top
R7410  57.6K_1%_2  [RSC_100X050X040_2]  240.52 100.44 90 top
R7412  31.6K_1%_2  [RSC_100X050X040_2]  241.46 109.97 270 top
R7414  3.3K_5%_2  [RSC_100X050X040_2]  243.87 102.47 90 top
R7415  3.3K_5%_2  [RSC_100X050X040_2]  245.9 102.73 270 top
R7416  3.3K_5%_2  [RSC_100X050X040_2]  152.18 155.69 270 bottom
R7418  13.7K_1%_2  [RSC_100X050X040_2]  242.35 112.25 90 top
R7425  51.1K_1%_2  [RSC_100X050X040_2]  246.79 100.44 270 top
R7426  16.2K_1%_2  [RSC_100X050X040_2]  245.02 100.44 270 top
R7428  3.3K_1%_2  [RSC_100X050X040_2]  245.9 100.44 270 top
R7600  RSC_0603_DY  [RSC_160X080X080_2]  269.15 129.4 90 bottom
R7610  RSC_0603_DY  [RSC_160X080X080_2]  200.06 159.88 180 bottom
R7615  RSC_0603_DY  [RSC_160X080X080_2]  241.21 158.99 180 bottom
R7620  RSC_0603_DY  [RSC_160X080X080_2]  158.27 150.35 180 bottom
R7627  1M_5%_2_DY  [RSC_100X050X040_2]  318.17 59.68 90 top
R7629  1M_5%_2_DY  [RSC_100X050X040_2]  316.77 78.47 180 top
R7630  RSC_0603_DY  [RSC_160X080X080_2]  131.22 101.84 0 bottom
R7631  1M_5%_2_DY  [RSC_100X050X040_2]  315.63 44.18 270 top
R7661  RSC_0603_DY  [RSC_160X080X080_2]  232.95 67.04 90 top
R9000  4.7K_5%_2  [RSC_100X050X040_2]  66.96 114.16 0 top
R9001  470_5%_2  [RSC_100X050X040_2]  66.96 113.27 0 top
R9002  100K_5%_2  [RSC_100X050X040_2]  73.31 120.13 270 top
R9011  short_0402_5  [RSC_100X050X040_2_SHORT]  70.64 120.13 90 top
R9012  0_5%_2_DY  [RSC_100X050X040_2]  71.53 120.13 90 top
R9031  270_5%_2  [RSC_100X050X040_2]  69.76 120.13 90 top
R9032  270_5%_2  [RSC_100X050X040_2]  68.61 120.13 270 top
R9033  270_5%_2  [RSC_100X050X040_2]  71.79 140.83 0 top
R9034  270_5%_2  [RSC_100X050X040_2]  75.6 123.05 0 top
R9035  10K_5%_2  [RSC_100X050X040_2]  75.6 125.72 180 top
R9036  1K_5%_2  [RSC_100X050X040_2]  75.6 126.6 180 top
R9037  100K_5%_2_DY  [RSC_100X050X040_2]  75.6 123.94 0 top
R9038  0_5%_2_DY  [RSC_100X050X040_2]  71.79 141.72 0 top
R9040  short_0402_15  [RSC_100X050X040_2_15_SHORT]  71.79 142.61 0 top
R9044  10K_5%_2  [RSC_100X050X040_2]  89.06 144.89 270 top
R9045  0_5%_2_DY  [RSC_100X050X040_2]  72.93 157.97 90 top
R9046  short_0402_15  [RSC_100X050X040_2_15_SHORT]  72.04 157.97 270 top
R9047  0_5%_2_DY  [RSC_100X050X040_2]  71.15 157.97 90 top
R9048  short_0402_15  [RSC_100X050X040_2_15_SHORT]  88.3 147.69 270 top
R9049  0_5%_2_DY  [RSC_100X050X040_2]  89.19 147.69 90 top
R9100  1K_5%_2  [RSC_100X050X040_2]  263.81 29.76 90 bottom
RS340  10k_5%  [RSC_368X216X050_10_064]  273.59 90.54 0 top
S0  -  [SCREW300_800_1P]  37.35 57 180 bottom
S1  -  [SCREW230_500_1P]  318.85 135.3 180 bottom
S2  -  [SCREW300_800_1P]  317.95 101 180 bottom
S3  -  [SCREW280_500_NP_1P]  328.85 59.45 270 bottom
S4  -  [SCREW300_800_1P]  321.35 17.5 180 bottom
S13  -  [SCREW230_600_NP_1P]  94.44 98.65 135 bottom
S14  -  [SCREW330_600_1P]  180.09 100.88 180 bottom
S15  -  [SCREW330_600_1P]  215.93 100.88 180 bottom
S16  -  [SCREW330_600_1P]  180.09 65.53 180 bottom
S17  -  [SCREW330_600_1P]  215.93 65.53 180 bottom
S25  -  [SCREW360_800_1P]  104.55 97.8 180 bottom
S26  -  [SCREW360_800_NP_1P]  235.35 100 90 bottom
S37  -  [SCREW300_800_NP_1P]  130.35 67 180 bottom
S38  -  [SCREW300_800_NP_1P]  234.85 52 270 bottom
S39  -  [SCREW300_800_NP_1P]  99.35 161.2 90 top
S41  -  [SCREW300_800_NP_1P]  259.35 161.2 90 top
S42  -  [SCREW230_600_NP_1P]  192.85 138.5 270 top
S9101  -  [SCREW230_600_1P]  274 31.15 0 bottom
S9102  -  [SCREW230_600_1P]  256.15 20.35 0 bottom
ST1  STDPAD_1.15_6-TOP  [STD_R_F45016_D10008_M20012_SN]  281.71 119.9 180 bottom
ST3  STDPAD_1.15_6-TOP  [STD_R_F45016_D10008_M20012_SN]  293.03 65.97 180 bottom
ST4  STDPAD_1.15_6-TOP  [STD_R_F45016_D10008_M20012_SN]  240.5 93.3 180 bottom
ST5  STDPAD_3.15_5.5_TOP  [STD_R_FF40016_D30010_M20026_SN]  258.51 93.3 0 top
SW152  MISAKI_NTC011_BA1J_A160T_4P  [SWCH-TACT_MISKI_5_SMD_V_170]  308.1 153.65 180 top
SW154  MISAKI_NTC011_BA1J_A160T_4P  [SWCH-TACT_MISKI_5_SMD_V_170]  320.5 153.65 180 top
SW9100  MISAKI_NTC011_BA1J_A160T_4P  [SWCH-TACT_MISKI_5_SMD_V_170]  260 26.35 180 bottom
TP2  -  [TP24]  290.53 114.92 270 top
TP7  -  [TP24]  292.01 116.44 270 top
TP8  -  [TP24]  292.01 114.92 270 top
TP10  -  [TP24]  290.53 116.44 270 top
TP290  TP40  [SMDTEST40]  110.14 128.76 0 top
TP291  TP40  [SMDTEST40]  107.6 128.76 0 top
TP292  TP40  [SMDTEST40]  104.81 129.14 0 top
TP293  TP40  [SMDTEST40]  108.11 126.35 0 top
TP294  TP40  [SMDTEST40]  102.39 129.14 0 top
TP303  -  [TP24]  127.03 81.52 0 top
TP304  -  [TP24]  267.37 108.06 180 bottom
TP332  -  [TP24]  270.8 91.43 0 top
TP640  TP40  [SMDTEST40]  248.95 156.32 0 top
TP641  TP40  [SMDTEST40]  247.05 155.05 0 top
TP642  TP40  [SMDTEST40]  249.08 153.78 0 top
TP643  TP40  [SMDTEST40]  246.29 152.77 0 top
TP1301  -  [TP24]  303.05 123.3 0 top
TP1302  -  [TP24]  301.53 123.43 0 top
TP1303  -  [TP24]  304.07 134.48 180 bottom
TP1951  -  [TP24]  294.67 98.08 0 top
TP3000  -  [TP24]  111.28 119.87 0 top
TP3065  -  [TP24]  80.55 86.98 0 top
TP3066  -  [TP24]  79.03 86.98 0 top
TP3067  -  [TP24]  80.55 85.46 0 top
TP3068  -  [TP24]  79.53 84.44 0 top
TP4500  -  [TP24]  198.03 69.84 180 bottom
TP4501  -  [TP24]  213.65 74.15 0 top
TP4502  -  [TP24]  210.22 80.76 0 top
TP4503  -  [TP24]  166.22 85.72 180 bottom
TP4504  -  [TP24]  167.45 86.52 180 bottom
TP4509  -  [TP24]  174.88 86.84 0 top
TP4531  -  [TP24]  168.31 70.98 180 bottom
TP4552  -  [TP24]  213.39 76.95 0 top
TP4553  -  [TP24]  214.79 76.95 0 top
TP4554  -  [TP24]  209.07 78.6 0 top
TP4555  -  [TP24]  212 76.95 0 top
TP4556  -  [TP24]  208.82 80 0 top
TP4557  -  [TP24]  210.85 79.23 0 top
TP4562  -  [TP24]  215.81 82.92 0 top
TP4563  -  [TP24]  211.11 82.15 0 top
TP4564  -  [TP24]  207.3 81.59 0 top
TP4565  -  [TP24]  209.07 81.9 0 top
TP4703  -  [TP24]  186.34 85.75 0 top
TP5300  -  [TP24]  278.67 69.2 180 bottom
TP5400  -  [TP24]  261.14 68.18 180 bottom
TP9001  -  [TP24]  87.79 154.16 180 top
TP9002  -  [TP24]  87.79 143.75 180 top
TP90664  -  [TP24]  192.69 89.77 0 top
TP90665  -  [TP24]  192.69 94.6 0 top
U300  SMSC_MEC1324_TQFP_128P  [TQFP_1400X1400X120_128_040]  269.91 102.73 90 top
U302  OSRAM_NL27WZ07DFT2G_SC88_6P_DY  [TSSC88_200X125X110_6_065]  262.41 87.49 0 top
U365  WINB_W25Q128FVSIQ_SOIC_8P  [SOP_528X528X216_8_127]  146.9 72.6 0 bottom
U366  WINBOND_W25Q16DVSSIG_8P  [SOP_523X528X216_8_127]  225.22 55.5 180 bottom
U400  INTEL_CLARKVILLE_I218_LM_48P  [QFN_600X600X090_48_040_T4]  292.77 110.35 0 top
U470  BOTH_NA0069RLF_SMD_24P  [SOP_1560X850X240_24_127]  305.31 96.89 270 top
U501  REALTEK_ALC3228_CG_QFN_48P  [QFN_600X600X100_48_040_T1]  301.4 60.06 270 top
U550  HP_HPA022642RTJ_QFN_20P  [QFN_400X400X080_20_050_T1]  308.13 73.77 0 top
U551  HP_HPA022642RTJ_QFN_20P  [QFN_400X400X080_20_050_T1]  311.69 60.82 270 top
U610  TI_TLV2462CDGKR_MSOP_8P_DY  [MSOP_305X483X110_8_065]  289.47 53.96 90 bottom
U800  REALTEK_RTS5237_GR_QFN_32P  [QFN_400X400X090_32_040_T1]  293.15 71.36 180 top
U1000  ST_HP3DC2TR_LGA_16P  [LGA_300X300X100_16_050]  243.49 96.89 90 top
U2400  ROHM_BD82034FVJ_GE2_MSOP_8P  [MSOP_300X300X110_8_065]  307.12 81.52 180 top
U2401  ROHM_BD82034FVJ_GE2_MSOP_8P  [MSOP_300X300X110_8_065]  320.07 40.5 270 bottom
U2402  TC7SZ08FU  [SSOP_200X125X100_5_065]  277.68 63.1 0 bottom
U2403  TC7SZ08FU  [SSOP_200X125X100_5_065]  275.37 63.1 0 bottom
U2511  TEXAS_TPS2546RTER_QFN_16P  [QFN_300X300X080_16_050_T1]  42.48 80.91 270 bottom
U2550  SMSC_USB5534B_6080JZX_QFN_64P  [QFN_900X900X100_64_050_T5]  272.96 59.8 0 top
U2551  MXIC_MX25L1606EM2I_12G_SOP_8P_DY  [SOP_523X528X216_8_127]  260.13 60.23 0 bottom
U2950  AZV331KTR_E1  [TSOT23_292X160X125_5_095]  249.97 111.11 0 top
U3000  NUVO_NCT3521U_SOT23_5P  [TSSOT23_290X160X135_5_095]  103.84 111.03 90 top
U3051  ROHM_BD82034FVJ_GE2_MSOP_8P  [MSOP_300X300X110_8_065]  38.51 70.98 180 bottom
U3065  NXP_PTN3355BS_HVQFN_40P  [HVQFN_600X600X100_40_050_T1]  84.89 86.66 180 top
U3300  NUVO_NCT3521U_SOT23_5P  [TSSOT23_290X160X135_5_095]  318.17 40.7 90 top
U3500  INFINEON_SLB9660TT1_2_TSSOP_28P  [TSSOP_970X440X110_28_065_P2]  123.48 148.58 180 bottom
U4411  GMT_G708T1U_SOT23_5P  [TSOT23_290X160X130_5_095]  46.77 87.36 180 top
U4555  INTEL_CL8064701477702_SR170_1168P  [CPU_INT_BDW_2CGT3_B_400X240]  192.85 85.2 180 bottom
U4700  TSB_TC7SH17F_SSOP_5P  [SSOP_290X160X140_5_095]  142.65 94.47 270 bottom
U5000  GMT_G780P81U_MSOP_8P  [MSOP_300X300X122_8_065]  113.83 92.67 90 bottom
U5301  PARADE_PS8338AQFN60GTR_QFN_60P  [QFN_900X500X080_60_040_T1]  282.86 73.52 90 bottom
U5401  PARADE_PS8338AQFN60GTR_QFN_60P  [QFN_900X500X080_60_040_T1]  266.61 73.52 90 bottom
U6000  TI_BQ24736RGRR_QFN_20P  [QFN_350X350X100_20_050_T1]  287.81 127.37 90 top
U6100  MPS_NB670GQ_QFN_16P  [QFN_300X300X100_14_040_T2]  204.08 154.28 180 bottom
U6150  MPS_NB676AGQ_QFN_16P  [QFN_300X300X100_14_040_T2]  237.77 148.82 90 bottom
U6200  ALPHA_OMEGA_AOZ1268QI_02_QFN_23P  [QFN_400X400X100_23_050_P3]  155.84 159.91 90 bottom
U6240  GMT_G2997RE1U_TDFN_10P  [TDFN_300X300X080_10_050_T5]  175.2 152.92 90 bottom
U6300  ALPHA_OMEGA_AOZ1268QI_02_QFN_23P  [QFN_400X400X100_23_050_P3]  124.24 98.16 90 bottom
U6350  RICHTEK_RT8068AZQW_WDFN_10P  [WDFN_300X300X080_10_050_T1]  100.36 145.4 270 top
U6450  RICHTEK_RT8068AZQW_WDFN_10P  [WDFN_300X300X080_10_050_T1]  247.81 86.47 180 top
U6600  TEXAS_TPS51622ARSMR_VQFN_32P  [QFN_400X400X100_32_040_T3]  230.41 80.25 270 bottom
U6610  TI_CSD97374CQ4M_SON_8P  [DB10SG-6019B0999601-002]  237.29 67.4 90 bottom
U6903  AZV331KTR_E1  [TSOT23_292X160X125_5_095]  296.83 136.38 180 top
U7000  TSB_TC7SZ07FU_SSOP_5P  [SSOP_200X125X100_5_065]  300.51 130.29 0 top
U7400  ON_LMV393DMR2G_SOP_8P  [MICRO_300X300X110_8_065]  241.33 104.89 0 top
U9000  ALCOR_AU9560B62_GBS_GR_SSOP_28P  [SSOP_1020X530X200_28_065]  73.44 113.65 0 top
U9100  BCD_AH9249NTR_G1_TSOT23_3P  [IC-HALL_BCD_3_SMD_V_145]  282.1 32.4 0 bottom
X400  25MHz_10pF  [XTAL_320X250X090_4_220-2]  295.82 100.95 270 top
X2500  25MHz_10pF  [XTAL_320X250X090_4_220-2]  263.68 55.1 180 top
X3065  27MHz_10pF  [XTAL_320X250X090_4-2]  91.38 83.9 270 top
X4750  32.768KHZ  [XPS_700X150X145_4]  161.2 102.09 180 bottom
X4751  24MHz_12pF  [XTAL_320X250X090_4_220-2]  188.78 64.76 90 bottom

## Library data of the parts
C100 C311 = CSC0402: part number: CSC0402-1UF_6.3V_2,6010B0006001,CSC_100X050X040_2,0.55MM,CSC0402,0402,X5R,CAP-CHIP,1UF,6.3V,K,X5R,0402,TR; signal model: C2_6010B0006001_1uF_6_3V_2; room: Sheet46
C131 C303 C308 C310 C312-C316 C366 = CSC0402: part number: CSC0402-0.1UF_16V_2,6010A0036403,CSC_100X050X040_2,0.55MM,CSC0402,0402,X7R,CAP-CHIP,0.1UF,16V,K,X7R,0402,TAP; signal model: C2_6010A0036403_0_1uF_16V_2; room: Sheet46
C301 C304 C306 C307 = CSC0402: part number: CSC0402-2200PF_50V_2,6010A0036305,CSC_100X050X040_2,0.55MM,CSC0402,0402,X7R,CAP-CHIP-2200PF-50V-K-X7R-0402-TAP; signal model: C2_6010A0036305_2200pF_50V_2; room: Sheet46
C302 = CSC0603: part number: CSC0603-1UF_25V_3,6010B0067601,CSC_160X080X080_2,0.95MM,CSC0603,0603,X5R,CAP-CHIP,1UF,25V,K,X5R,0603,TR; signal model: C2_6010B0067601_1uF_25V_3; room: Sheet46
C305 = CSC0402: part number: CSC0402-0.1UF_16V_2,6010A0036403,CSC_100X050X040_2,0.55MM,CSC0402,0402,X7R,CAP-CHIP,0.1UF,16V,K,X7R,0402,TAP; signal model: C2_6010A0036403_0_1uF_16V_2; room: Sheet47
C320 C321 = CSC0402: part number: CSC0402-0.1UF_16V_2_DY,6010A0036403_DY,CSC_100X050X040_2,0.55MM,CSC0402,0402,X7R,CAP-CHIP,0.1UF,16V,K,X7R,0402,TAP; signal model: C2_6010A0036403_DY_0_1uF_16V_2_DY; room: Sheet46
C335 = CSC0402: part number: CSC0402-0.1UF_16V_2_DY,6010A0036403_DY,CSC_100X050X040_2,0.55MM,CSC0402,0402,X7R,CAP-CHIP,0.1UF,16V,K,X7R,0402,TAP; signal model: C2_6010A0036403_DY_0_1uF_16V_2_DY; room: Sheet47
C400 C404 = CSC0402: part number: CSC0402-10PF_50V_2,6010A0025401,CSC_100X050X040_2,0.55MM,CSC0402,0402,NPO,CAP-CHIP-10PF-D,50V-NPO-0402-TAP; signal model: C2_6010A0025401_10pF_50V_2; room: Sheet49
C401 C403 C407 C408 C475-C478 = CSC0402: part number: CSC0402-0.1UF_16V_2,6010A0036403,CSC_100X050X040_2,0.55MM,CSC0402,0402,X7R,CAP-CHIP,0.1UF,16V,K,X7R,0402,TAP; signal model: C2_6010A0036403_0_1uF_16V_2; room: Sheet49
C402 C479 = CSC0402: part number: CSC0402-1UF_6.3V_2,6010B0006001,CSC_100X050X040_2,0.55MM,CSC0402,0402,X5R,CAP-CHIP,1UF,6.3V,K,X5R,0402,TR; signal model: C2_6010B0006001_1uF_6_3V_2; room: Sheet49
C409 = CSC0805: part number: CSC0805-22UF_6.3V_5,6010A0040702,CSC_200X125X130_2,1.45MM,CSC0805,0805,X5R,CAP-CHIP-22UF-6.3V-M-X5R-0805-TAP; signal model: C2_6010A0040702_22uF_6_3V_5; room: Sheet49
C470-C473 = CSC0603: part number: CSC0603-0.01UF_100V_3,6010B0044801,CSC_160X080X080_2,0.95MM,CSC0603,0603,X7R,CAP-CHIP-0.01UF,100V,M,X7R,0603,TR; signal model: C2_6010B0044801_0_01uF_100V_3; room: Sheet49
C474 = CSC_SPECIAL: part number: CSC_SPECIAL-100PF_3000V,6010A0014801,CSC_460X200X180_2,1.95MM,CSC_SPECIAL,,,CAPACITOR-CHIP-100PF-K,3000V-NPO-1808-TA; signal model: C2_6010A0014801_100PF_3000V; room: Sheet49
C486 = CSC0402: part number: CSC0402-0.1UF_25V_2,6010B0087101,CSC_100X050X040_2,0.55MM,CSC0402,0402,X5R,CAP-CHIP,0.1UF,25V,K,X5R,0402,TR; signal model: C2_6010B0087101_0_1uF_25V_2; room: Sheet49
C501 C502 C506 C508 C510 C512 C513 = CSC0603: part number: CSC0603-10UF_6.3V_3,6010B0044901,CSC_160X080X080_2,0.95MM,CSC0603,0603,X5R,CAP-CHIP,10UF,6.3V,M,X5R,0603,TR; signal model: C2_6010B0044901_10uF_6_3V_3; room: Sheet54
C503 C505 C507 C509 C511 C515 C517 C518 C527 C529 = CSC0402: part number: CSC0402-0.1UF_16V_2,6010A0036403,CSC_100X050X040_2,0.55MM,CSC0402,0402,X7R,CAP-CHIP,0.1UF,16V,K,X7R,0402,TAP; signal model: C2_6010A0036403_0_1uF_16V_2; room: Sheet54
C504 C516 C521 = CSC0603: part number: CSC0603-2.2UF_6.3V_3,6010B0027401,CSC_160X080X090_2,1.05MM,CSC0603,0603,X5R,CAPACITOR-CHIP,2.2UF,6.3V,K,X5R,0603,TR; signal model: C2_6010B0027401_2_2uF_6_3V_3; room: Sheet54
C514 C526 = CSC0603: part number: CSC0603-4.7UF_6.3V_3,6010B0009904,CSC_160X080X080_2,0.95MM,CSC0603,0603,X5R,CAP-CHIP,4.7UF,6.3V,K,X5R,0603,TR; signal model: C2_6010B0009904_4_7uF_6_3V_3; room: Sheet54
C519 = CSC0402: part number: CSC0402-100PF_50V_2,6010071012AT,CSC_100X050X040_2,0.55MM,CSC0402,0402,NPO,CAP-CHIP-101-J,50V-NPO-0402; signal model: C2_6010071012AT_100pF_50V_2; room: Sheet54
C523 = CSC0402: part number: CSC0402-10PF_50V_2_DY,6010A0025401_DY,CSC_100X050X040_2,0.55MM,CSC0402,0402,NPO,CAP-CHIP-10PF-D,50V-NPO-0402-TAP; signal model: C2_6010A0025401_DY_10pF_50V_2_DY; room: Sheet54
C532 = CSC0402: part number: CSC0402-1UF_6.3V_2,6010B0006001,CSC_100X050X040_2,0.55MM,CSC0402,0402,X5R,CAP-CHIP,1UF,6.3V,K,X5R,0402,TR; signal model: C2_6010B0006001_1uF_6_3V_2; room: Sheet54
C550 C552 C554 C562 C564 C566 C569 C570 C572 C573 = CSC0402: part number: CSC0402-1UF_6.3V_2,6010B0006001,CSC_100X050X040_2,0.55MM,CSC0402,0402,X5R,CAP-CHIP,1UF,6.3V,K,X5R,0402,TR; signal model: C2_6010B0006001_1uF_6_3V_2; room: Sheet55
C551 C555 C563 C567 = CSC0402: part number: CSC0402-0.1UF_16V_2,6010A0036403,CSC_100X050X040_2,0.55MM,CSC0402,0402,X7R,CAP-CHIP,0.1UF,16V,K,X7R,0402,TAP; signal model: C2_6010A0036403_0_1uF_16V_2; room: Sheet55
C553 C565 = CSC0603: part number: CSC0603-2.2UF_6.3V_3,6010B0027401,CSC_160X080X090_2,1.05MM,CSC0603,0603,X5R,CAPACITOR-CHIP,2.2UF,6.3V,K,X5R,0603,TR; signal model: C2_6010B0027401_2_2uF_6_3V_3; room: Sheet55
C560 C561 = CSC0603: part number: CSC0603-10UF_6.3V_3,6010B0044901,CSC_160X080X080_2,0.95MM,CSC0603,0603,X5R,CAP-CHIP,10UF,6.3V,M,X5R,0603,TR; signal model: C2_6010B0044901_10uF_6_3V_3; room: Sheet55
C574 C575 = CSC0402: part number: CSC0402-100PF_50V_2,6010071012AT,CSC_100X050X040_2,0.55MM,CSC0402,0402,NPO,CAP-CHIP-101-J,50V-NPO-0402; signal model: C2_6010071012AT_100pF_50V_2; room: Sheet55
C601 C602 = CSC0402: part number: CSC0402-0.033UF_16V_2,6010B0010101,CSC_100X050X040_2,0.55MM,CSC0402,0402,X7R,CAP-CHIP,0.033UF,16V,K,X7R,0402,TR; signal model: C2_6010B0010101_0_033uF_16V_2; room: Sheet55
C603 = CSC0402: part number: CSC0402-220PF_50V_2,6010B0076701,CSC_100X050X040_2,0.55MM,CSC0402,0402,C0G,CAP-CHIP,220PF,50V,J,C0G,0402,TR; signal model: C2_6010B0076701_220pF_50V_2; room: Sheet55
C604 = CSC0402: part number: CSC0402-1UF_6.3V_2,6010B0006001,CSC_100X050X040_2,0.55MM,CSC0402,0402,X5R,CAP-CHIP,1UF,6.3V,K,X5R,0402,TR; signal model: C2_6010B0006001_1uF_6_3V_2; room: Sheet64
C605 = CSC0603: part number: CSC0603-4.7UF_6.3V_3,6010B0009904,CSC_160X080X080_2,0.95MM,CSC0603,0603,X5R,CAP-CHIP,4.7UF,6.3V,K,X5R,0603,TR; signal model: C2_6010B0009904_4_7uF_6_3V_3; room: Sheet55
C612 = CSC0402: part number: CSC0402-15PF_50V_2_DY,6010071502AT_DY,CSC_100X050X040_2,0.55MM,CSC0402,0402,NPO,CAP-CHIP,15PF,J-50V-NPO-0402-TAP; signal model: C2_6010071502AT_15pF_50V_2_DY; room: Sheet55
C613 = CSC0402: part number: CSC0402-2.2UF_6.3V_2_DY,6010B0059301_DY,CSC_100X050X040_2,0.55MM,CSC0402,0402,X5R,CAP-CHIP,2.2UF,6.3V,M,X5R,0402,TR; signal model: C2_6010B0059301_DY_2_2uF_6_3V_2_DY; room: Sheet55
C614 C615 = CSC0402: part number: CSC0402-0.1UF_16V_2_DY,6010A0036403_DY,CSC_100X050X040_2,0.55MM,CSC0402,0402,X7R,CAP-CHIP,0.1UF,16V,K,X7R,0402,TAP; signal model: C2_6010A0036403_DY_0_1uF_16V_2_DY; room: Sheet55; signal model: C2_6010A0036403_0_1uF_16V_2
C616 = CSC0402: part number: CSC0402-100PF_50V_2_DY,6010071012AT_DY,CSC_100X050X040_2,0.55MM,CSC0402,0402,NPO,CAP-CHIP-101-J,50V-NPO-0402; signal model: C2_6010071012AT_DY_100pF_50V_2_DY; room: Sheet55
C617 = CSC0402: part number: CSC0402-68PF_50V_2_DY,60100768020T_DY,CSC_100X050X040_2,0.55MM,CSC0402,0402,C0G,CAP-CHIP-680-J,50V-TAP(0402); signal model: C2_60100768020T_68pF_50V_2_DY; room: Sheet55
C627 = CSC0603: part number: CSC0603-2.2UF_10V_3,6010B0011501,CSC_160X080X080_2,0.95MM,CSC0603,0603,X5R,CAP-CHIP,2.2UF,10V,K,X5R,0603,TR; signal model: C2_6010B0011501_2_2uF_10V_3; room: Sheet55
C640-C643 = CSC0402: part number: CSC0402-1000PF_50V_2,6010071020AT,CSC_100X050X055_2,0.7MM,CSC0402,0402,X7R,CAPACITOR-CHIP,1000PF,50V,K,X7R,0402,TR; signal model: C2_6010071020AT_1000PF_50V_2; room: Sheet54
C650 C652 = CSC0402: part number: CSC0402-1000PF_50V_2,6010071020AT,CSC_100X050X055_2,0.7MM,CSC0402,0402,X7R,CAPACITOR-CHIP,1000PF,50V,K,X7R,0402,TR; signal model: C2_6010071020AT_1000PF_50V_2; room: Sheet64
C651 C653 = CSC0603: part number: CSC0603-4.7UF_6.3V_3,6010B0009904,CSC_160X080X080_2,0.95MM,CSC0603,0603,X5R,CAP-CHIP,4.7UF,6.3V,K,X5R,0603,TR; signal model: C2_6010B0009904_4_7uF_6_3V_3; room: Sheet64
C800 C803 C805 C806 C810 C811 C813 = CSC0402: part number: CSC0402-0.1UF_16V_2,6010A0036403,CSC_100X050X040_2,0.55MM,CSC0402,0402,X7R,CAP-CHIP,0.1UF,16V,K,X7R,0402,TAP; signal model: C2_6010A0036403_0_1uF_16V_2; room: Sheet56
C801 C807 = CSC0603: part number: CSC0603-4.7UF_6.3V_3,6010B0009904,CSC_160X080X080_2,0.95MM,CSC0603,0603,X5R,CAP-CHIP,4.7UF,6.3V,K,X5R,0603,TR; signal model: C2_6010B0009904_4_7uF_6_3V_3; room: Sheet56
C802 = CSC0402: part number: CSC0402-1UF_6.3V_2,6010B0006001,CSC_100X050X040_2,0.55MM,CSC0402,0402,X5R,CAP-CHIP,1UF,6.3V,K,X5R,0402,TR; signal model: C2_6010B0006001_1uF_6_3V_2; room: Sheet56
C804 C808 = CSC0603: part number: CSC0603-10UF_6.3V_3,6010B0044901,CSC_160X080X080_2,0.95MM,CSC0603,0603,X5R,CAP-CHIP,10UF,6.3V,M,X5R,0603,TR; signal model: C2_6010B0044901_10uF_6_3V_3; room: Sheet56
C1000 = CSC0603: part number: CSC0603-10UF_6.3V_3,6010B0044901,CSC_160X080X080_2,0.95MM,CSC0603,0603,X5R,CAP-CHIP,10UF,6.3V,M,X5R,0603,TR; signal model: C2_6010B0044901_10uF_6_3V_3; room: Sheet45
C1001 = CSC0402: part number: CSC0402-0.1UF_16V_2,6010A0036403,CSC_100X050X040_2,0.55MM,CSC0402,0402,X7R,CAP-CHIP,0.1UF,16V,K,X7R,0402,TAP; signal model: C2_6010A0036403_0_1uF_16V_2; room: Sheet45
C1301 C1304 = CSC0402: part number: CSC0402-0.1UF_16V_2,6010A0036403,CSC_100X050X040_2,0.55MM,CSC0402,0402,X7R,CAP-CHIP,0.1UF,16V,K,X7R,0402,TAP; signal model: C2_6010A0036403_0_1uF_16V_2; room: Sheet50
C1303 = CSC0603: part number: CSC0603-10UF_6.3V_3,6010B0044901,CSC_160X080X080_2,0.95MM,CSC0603,0603,X5R,CAP-CHIP,10UF,6.3V,M,X5R,0603,TR; signal model: C2_6010B0044901_10uF_6_3V_3; room: Sheet50
C1305 = CSC0402: part number: CSC0402-0.01UF_50V_2,6010B0058401,CSC_100X050X040_2,0.55MM,CSC0402,0402,X7R,CAP-CHIP,0.01UF,50V,K,X7R,0402,TAP; signal model: C2_6010B0058401_0_01uF_50V_2; room: Sheet50
C1307 = CSC0603: part number: CSC0603-4.7UF_6.3V_3,6010B0009904,CSC_160X080X080_2,0.95MM,CSC0603,0603,X5R,CAP-CHIP,4.7UF,6.3V,K,X5R,0603,TR; signal model: C2_6010B0009904_4_7uF_6_3V_3; room: Sheet50
C1308 = CSC0402: part number: CSC0402-0.1UF_16V_2_DY,6010071041BT_DY,CSC_100X050X055_2,0.7MM,CSC0402,0402,,CAP-CHIP-104-Z,16V-TAP(0402); signal model: C2_6010071041BT_DY_0_1uF_16V_2_DY; room: Sheet50
C1402 = CSC0402: part number: CSC0402-0.1UF_16V_2_DY,6010A0036403_DY,CSC_100X050X040_2,0.55MM,CSC0402,0402,X7R,CAP-CHIP,0.1UF,16V,K,X7R,0402,TAP; signal model: C2_6010A0036403_DY_0_1uF_16V_2_DY; room: Sheet51
C1405 C1453 = CSC0402: part number: CSC0402-18PF_50V_2_DY,6010A0036105_DY,CSC_100X050X040_2,0.55MM,CSC0402,0402,NPO,CAP-CHIP-18PF-50V-J-NPO-0402-TAP; signal model: C2_6010A0036105_DY_18pF_50V_2_DY; room: Sheet51
C1413 = CSC0402: part number: CSC0402-0.01UF_50V_2,6010B0058401,CSC_100X050X040_2,0.55MM,CSC0402,0402,X7R,CAP-CHIP,0.01UF,50V,K,X7R,0402,TAP; signal model: C2_6010B0058401_0_01uF_50V_2; room: Sheet51
C1414 C1451 = CSC0402: part number: CSC0402-0.1UF_16V_2,6010A0036403,CSC_100X050X040_2,0.55MM,CSC0402,0402,X7R,CAP-CHIP,0.1UF,16V,K,X7R,0402,TAP; signal model: C2_6010A0036403_0_1uF_16V_2; room: Sheet51
